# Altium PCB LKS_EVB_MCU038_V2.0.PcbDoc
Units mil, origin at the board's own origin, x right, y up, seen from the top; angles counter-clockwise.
Board outline 2625 x 1560 mil, 2 copper layers (Top Layer, Bottom Layer); 32 components, 46 nets, 145 pads, 22 vias.
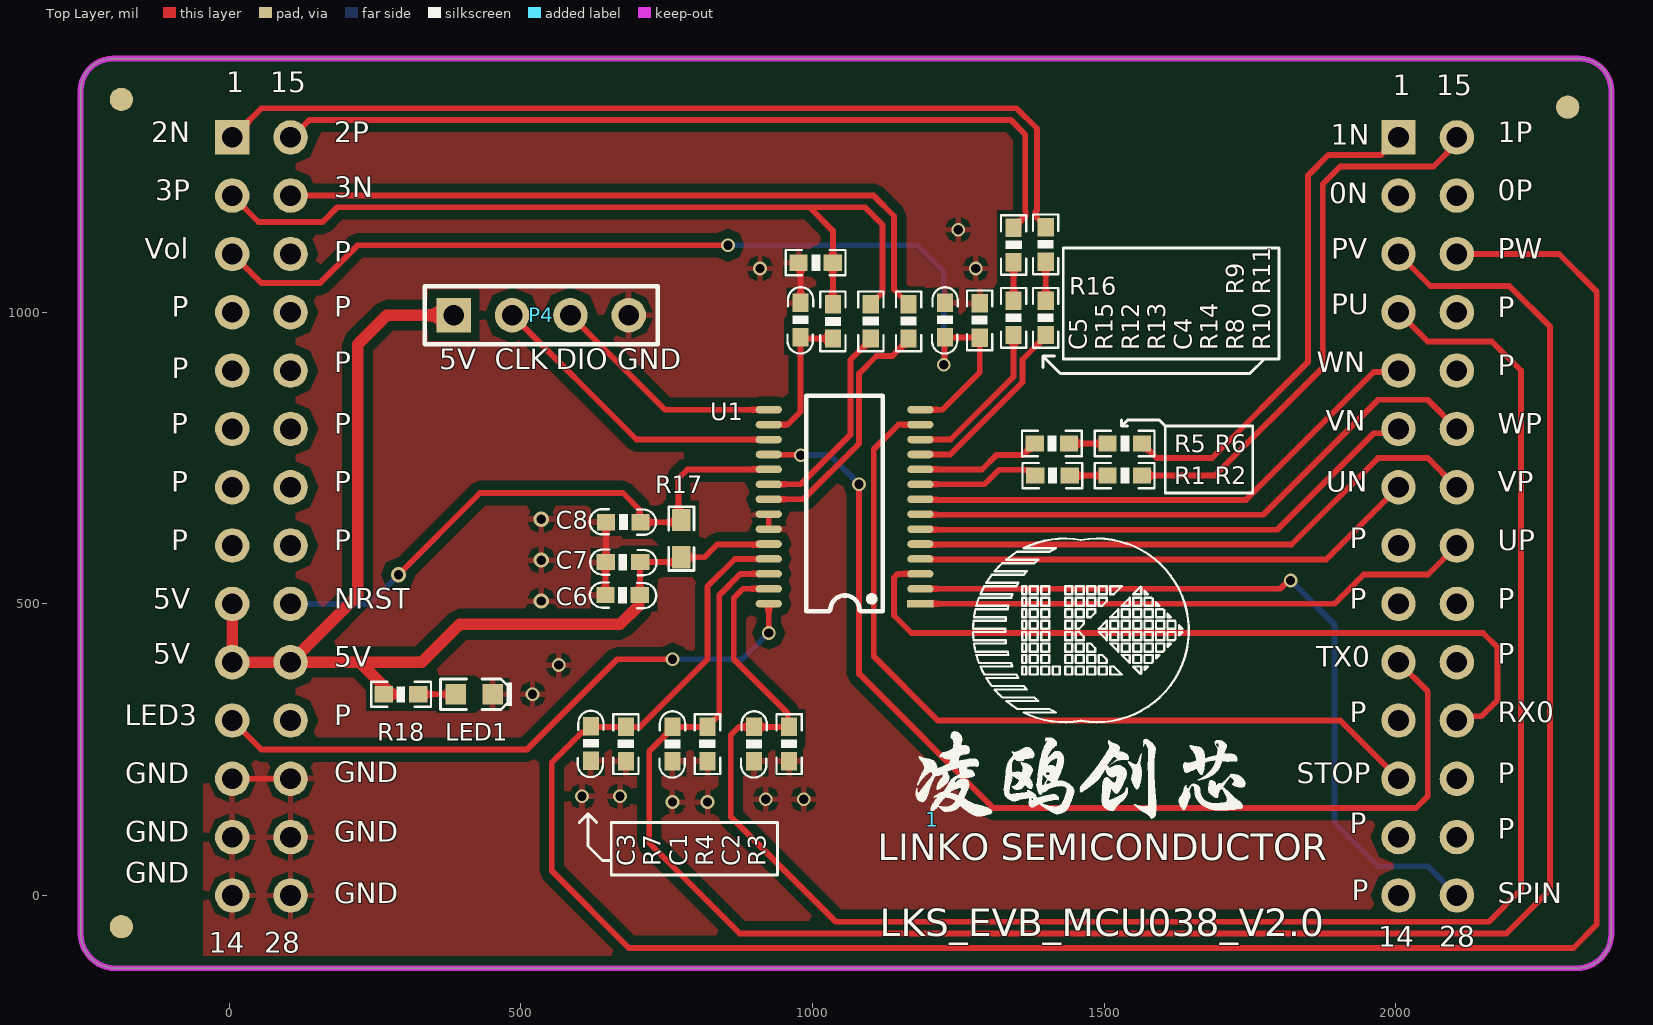
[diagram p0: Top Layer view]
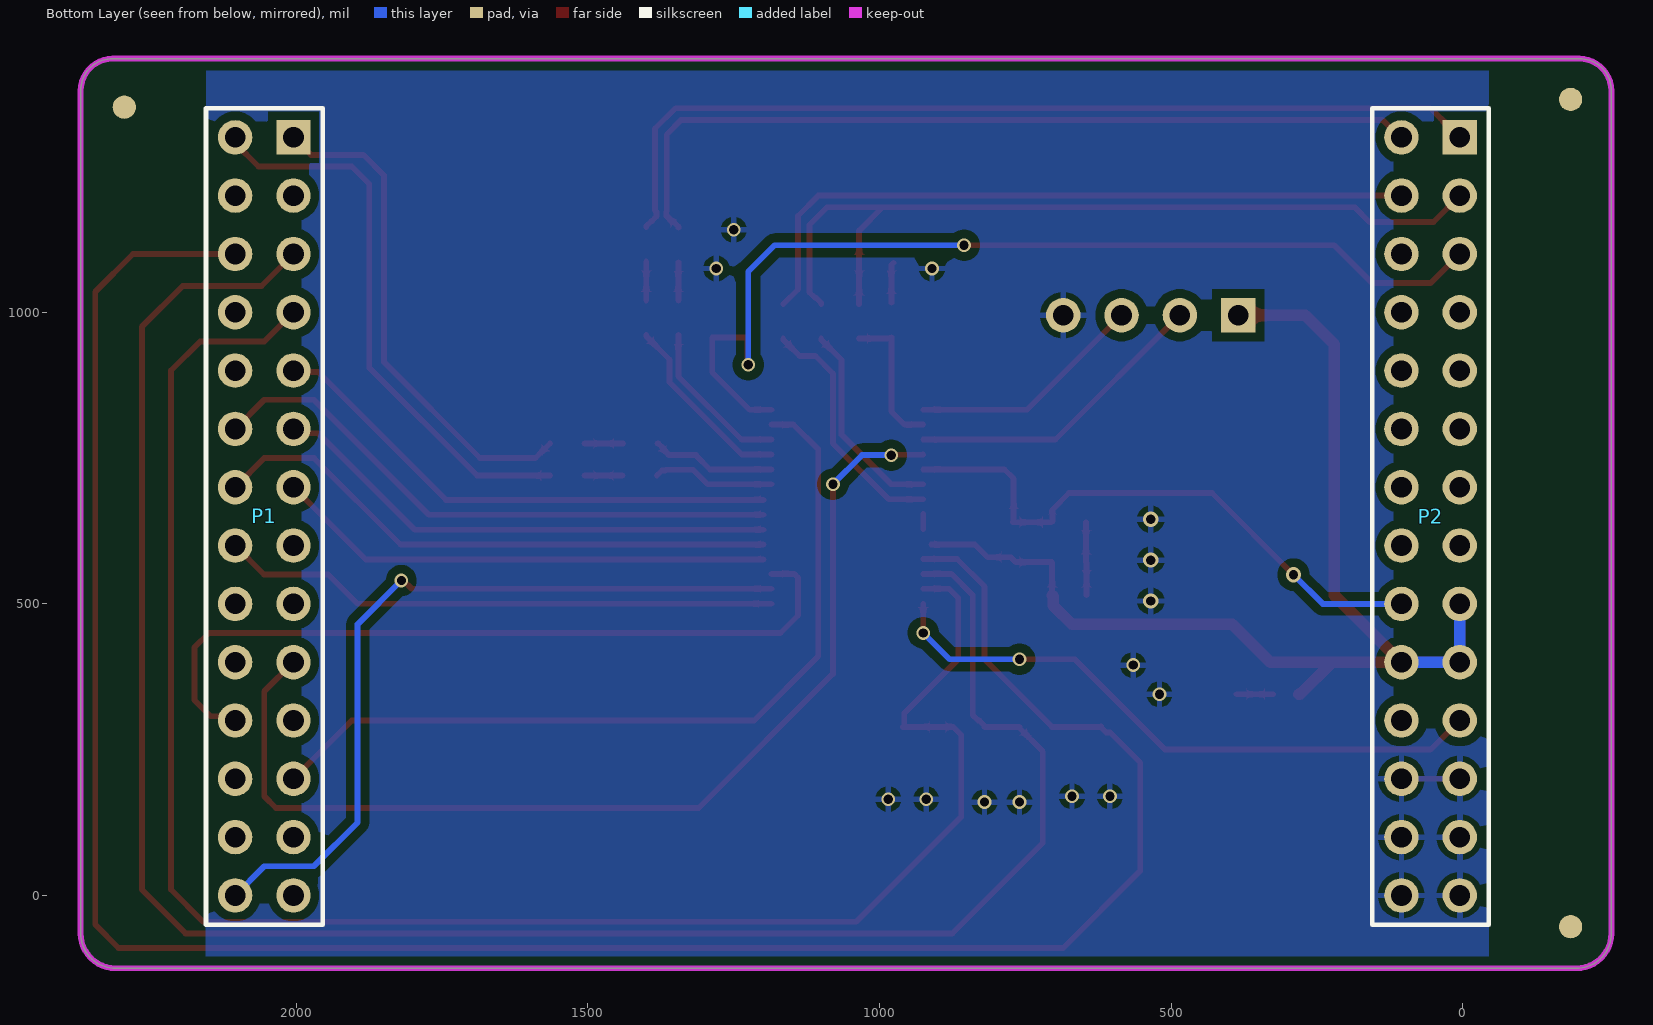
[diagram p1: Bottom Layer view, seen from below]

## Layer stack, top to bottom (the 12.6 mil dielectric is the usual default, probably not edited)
Top Solder: solder mask 0.4, Solder Resist, Dk 3.5
Top Layer: signal copper 1.4
Dielectric 1: dielectric 12.6, FR-4, Dk 4.8
Bottom Layer: signal copper 1.4
Bottom Solder: solder mask 0.4, Solder Resist, Dk 3.5

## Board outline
-255,-65 ccw(c-195,-65) -195,-125 2310,-125 ccw(c2310,-65) 2370,-65 2370,1380 ccw(c2315,1380) 2315,1435 -200,1435 ccw(c-200,1380) -255,1380

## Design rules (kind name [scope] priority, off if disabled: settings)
Clearance Clearance_1 [InPolygon] p1: gap=15 ignorepadtopadclearanceinfootprint=FALSE
Clearance [All] p2: gap=7.87 ignorepadtopadclearanceinfootprint=FALSE
ComponentClearance [All] p1: gap=0 collisioncheckmode=3 verticalgap=0 showdistances=FALSE
DiffPairsRouting DiffPair_DiffPairsRouting [All] p1: maxlimit=10 minlimit=10 mostfreqgap=10 toplayer_minwidth=10 toplayer_maxwidth=10 toplayer_prefwidth=10 bottomlayer_minwidth=10 bottomlayer_maxwidth=10 bottomlayer_prefwidth=10 maxuncoupledlength=500
DiffPairsRouting [All] p2: maxlimit=10 minlimit=10 mostfreqgap=10 toplayer_minwidth=15 toplayer_maxwidth=15 toplayer_prefwidth=15 bottomlayer_minwidth=15 bottomlayer_maxwidth=15 bottomlayer_prefwidth=15 maxuncoupledlength=500
MatchedLengths DiffPair_MatchedLengths [All] p1: tolerance=1000 checknetsindiffpair=TRUE checkdiffpairvsdiffpair=FALSE checkxsignals=FALSE checkothers=FALSE
PolygonConnect [All] p1: connectstyle=Relief reliefconductorwidth=10 reliefentries=4 polygonreliefangle="90 Angle" airgapwidth=10
RoutingVias [All] p1: holewidth=28 width=50 viastyle="Through Hole" minholewidth=28 minwidth=50 maxholewidth=28 maxwidth=50
SolderMaskExpansion [All] p1: expansion=4 istentingtop=FALSE
Width [All] p1: maxlimit=100 minlimit=1 preferedwidth=10
28 further rules are at their usual default settings.

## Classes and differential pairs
differential pair OPA2: +OPA2_P -OPA2_N

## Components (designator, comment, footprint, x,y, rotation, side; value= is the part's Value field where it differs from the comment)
1 "LKS_sign" LKS_LOGO2 1205,130 r0 top
C1 "1nF/16V" 0603C 760,289.06 r270 top
C2 "1nF/16V" 0603C 900,289.06 r270 top
C3 "1nF/16V" 0603C 620,290 r270 top
C4 "100nF/50V" 0603C 1227.36,1016.1 r270 top
C5 "1nF/50V" 0603C 979.71,1016.35 r270 top
C6 "10uF/10V" 0603C 645,515 r0 top
C7 "100nF/50V" 0603C 645.55,571.57 r0 top
C8 "100nF/50V" 0603C 705,640 r180 top
LED1 "LED" 0603D 420,345 r0 top
P1 "Header 14X2A" HDR2X14_CEN 2005,1300 r270 bottom
P2 "Header 14X2A" HDR2X14_CEN 5,1300 r270 bottom
P4 "Header 4" HDR1X4 385,995 r0 top
R1 "20K1%" 0603R#1 1440.94,720 r180 top value=K
R2 "20K1%" 0603R#1 1565,720 r180 top value=K
R3 "1K1%" 0603R#1 960,289.06 r270 top value=K
R4 "1K1%" 0603R#1 820,289.06 r270 top value=K
R5 "20K1%" 0603R#1 1440,775 r180 top value=K
R6 "20K1%" 0603R#1 1565,775 r180 top value=K
R7 "1K1%" 0603R#1 680,289.06 r270 top value=K
R8 "20K1%" 0603R#1 1345,1020 r270 top value=K
R9 "20K1%" 0603R#1 1345,1145 r270 top value=K
R10 "20K1%" 0603R#1 1400,1020 r270 top value=K
R11 "20K1%" 0603R#1 1400,1145.94 r270 top value=K
R12 "1K1%" 0603R#1 1100,1014.06 r270 top value=K
R13 "1K1%" 0603R#1 1165,1014.06 r270 top value=K
R14 "1K1%" 0603R#1 1286.81,1015.71 r270 top value=K
R15 "1K1%" 0603R#1 1035,955 r90 top value=K
R16 "10R" 0603R#1 1035,1085 r180 top value=K
R17 "20K1%" 0603R#2 775,612 r270 top value=K
R18 "330R" 0603R#1 265,345 r0 top value=330
U1 "037E" TSSOP-28 1186.63,498.48 r180 top

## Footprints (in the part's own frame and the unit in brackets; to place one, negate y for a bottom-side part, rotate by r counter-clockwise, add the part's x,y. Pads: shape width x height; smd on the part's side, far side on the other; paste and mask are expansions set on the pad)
0603C [mm]
  rect 0.8x0.7 smd: 1(0,0) 2(1.5,0)
  silkscreen extent -0.68,-0.57 2.21,0.55
0603D [mm]
  rect 0.9x0.9 smd: 1(-0.813,0) 2(0.813,0)
  silkscreen extent -1.47,-0.66 1.65,0.66
0603R#1 [mm]
  rect 0.8x0.7 smd: 1(0,0) 2(1.5,0)
  silkscreen extent -0.55,-0.55 2.05,0.55
0603R#2 [mm]
  rect 0.965x0.813 smd: 1(-0.813,0) 2(0.813,0)
  silkscreen extent -1.38,-0.55 1.38,0.55
HDR1X4 [mm] "Connector; Header; 4 Position"
  rect 1.5x1.5 hole 0.9: 1(0,0)
  round 1.5 hole 0.9: 2(2.54,0) 3(5.08,0) 4(7.62,0)
  silkscreen extent -1.27,-1.27 8.89,1.27
HDR2X14_CEN [mm] "Connector; Header; 14x2 Position"
  rect 1.5x1.5 hole 0.9: 1(0,0)
  round 1.5 hole 0.9: 2(2.54,0) 3(5.08,0) 4(7.62,0) 5(10.16,0) 6(12.7,0) 7(15.24,0) 8(17.78,0) 9(20.32,0) 10(22.86,0) 11(25.4,0) 12(27.94,0) 13(30.48,0) 14(33.02,0) 15(0,-2.54) 16(2.54,-2.54) 17(5.08,-2.54) 18(7.62,-2.54) 19(10.16,-2.54) 20(12.7,-2.54) 21(15.24,-2.54) 22(17.78,-2.54) 23(20.32,-2.54) 24(22.86,-2.54) 25(25.4,-2.54) 26(27.94,-2.54) 27(30.48,-2.54) 28(33.02,-2.54)
  silkscreen extent -1.27,-3.81 34.29,1.27
LKS_LOGO2 [mil] "标?"
  silkscreen extent 70,167 440,482
TSSOP-28 [mil] "9.70x4.40x1.00 e=0.65（蒜米工坊）"
  rect 45x12.99 smd: 1(1.63,-1.8)
  oval 45x12.99 smd: 2(1.63,-27.39) 3(1.63,-52.98) 4(1.63,-78.57) 5(1.63,-104.16) 6(1.63,-129.75) 7(1.63,-155.34) 8(1.63,-180.93) 9(1.63,-206.52) 10(1.63,-232.11) 11(1.63,-257.7) 12(1.63,-283.29) 13(1.63,-308.88) 14(1.63,-334.47) 15(261.47,-334.47) 16(261.47,-308.88) 17(261.47,-283.29) 18(261.47,-257.7) 19(261.47,-232.11) 20(261.47,-206.52) 21(261.47,-180.93) 22(261.47,-155.34) 23(261.47,-129.75) 24(261.47,-104.16) 25(261.47,-78.57) 26(261.47,-52.98) 27(261.47,-27.39) 28(261.47,-1.8)
  silkscreen extent 66,-358 197,11, body extent 2,-360 254,26, height 41

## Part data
C1 C2 C3: library part CAP, "Capacitor"
C4 C5 C6 C7 C8: library part C, "Capacitor"
LED1: "LED_Light"
P1 P2: "Header, 14-Pin, Dual row"
P4: "Header, 4-Pin"
R1 R2 R3 R4 R5 R6 R7 R8 R9 R10 R11 R12 R13 R14 R15 R16 R17 R18: library part Res, "Resistor"
U1: library part LKS32MC038Y6P8, "CHIP--TSSOP28"

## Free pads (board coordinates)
  round 40 all layers, no hole: 2(2295,1351.86) 3(-185,-53.57) 4(-185,1365)

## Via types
v1: diameter 23.62, hole 15.75, Top Layer to Bottom Layer, 18 vias
v2: diameter 26, hole 16, Top Layer to Bottom Layer, 4 vias

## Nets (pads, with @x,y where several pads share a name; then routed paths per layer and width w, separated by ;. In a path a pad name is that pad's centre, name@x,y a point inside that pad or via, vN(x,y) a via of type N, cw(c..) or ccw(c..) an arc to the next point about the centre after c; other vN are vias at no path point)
+5V: C6.2 C7.2 P2.9 P2.10 P2.24 P4.1 R17.2 R18.1 U1.24 | length 2190.1
  Top Layer w10: C6.2 704.06,571.02 C7.2 766.57,571.57 R17.2 815,580 836.61,601.61 U1.24@911.3,601.61
  Top Layer w20: P2.9 P2.10 P2.24 ; 280.94,345 278.98,345 223.98,400 ; P4.1 270,995 220,945 220,515 P2.24 ; C6.2 701.94,512.88 701.94,496.94 670,465 395,465 330,400 223.98,400 ; P2.24 223.98,400
  Bottom Layer w20: P2.9 P2.10 P2.24
GND: C1.2 C2.2 C3.2 C4.1 C5.1 C6.1 C7.1 C8.2 LED1.2 P2.12 P2.13 P2.14 P2.26 P2.27 P2.28 P4.4 R3.2 R4.2 R7.2 R14.1 R16.2 U1.22 U1.23 | length 321.2
  Top Layer w10: P2.12 P2.26 ; C6.1 645,571.02 C7.1 645.94,571.97 C8.2 ; U1.23 U1.22 ; R16.2 979.71,1081.24 C5.1
  other v1: 760,160 820,160 920,165 985,165 605,170 670,170 520,345 565,395 910,1075 1280,1075 1250,1141.54
  other v2: 535,505 535,575 535,645
GND0: P2.16 R13.1 | length 1210.8
  Top Layer w10: P2.16 1105,1200 1140,1165 1140,1039.06 R13.1
HALL_U: P2.8
HALL_V: P2.7
HALL_W: P2.6
HU: P2.21
HV: P2.20
HW: P2.19
LED3: P2.11 U1.28 | length 1074.1
  Top Layer w10: P2.11 55,250 510,250 665,405 v1(760,405) ; v1@925,450 v1(925.16,450.16) U1.28
  Bottom Layer w10: v1(760,405) 880,405 v1(925.16,450.16)
NetLED1_1: LED1.1 R18.2 | length 63
  Top Layer w10: R18.2@325,345 LED1.1
NetR1_1: R1.1 R2.2 | length 65
  Top Layer w10: R1.1 R2.2
NetR5_1: R5.1 R6.2 | length 65.9
  Top Layer w10: R5.1 R6.2
NetR8_1: R8.1 R9.2 | length 65.9
  Top Layer w10: R8.1 R9.2
NetR10_1: R10.1 R11.2 | length 66.9
  Top Layer w10: R10.1 R11.2
NRST: C8.1 P2.23 R17.1 U1.19 | length 1014.2
  Top Layer w10: v2(290,550) 430,690 675,690 703.58,661.42 703.58,641.42 C8.1 771,640 770,641 770,715 785.59,730.59 U1.19
  Bottom Layer w10: P2.23 240,500 v2(290,550)
OC: C5.2 R15.1 U1.16 | length 247.6
  Top Layer w10: U1.16 957.36,807.36 979.71,829.71 C5.2 982,955 R15.1
OPA0_IN: R13.2 U1.21 | length 425.4
  Top Layer w10: U1.21 984.41,679.41 1080,775 1080,895 1110,925 1136.97,925 1165,953.03 R13.2
OPA0_IP: R12.2 U1.20 | length 354.5
  Top Layer w10: U1.20 980,705 1065,790 1065,918.03 1100,953.03 R12.2
OPA2_N: R5.2 U1.10 | length 215.5
  Top Layer w10: U1.10 1290.59,730.59 1315,755 1360.94,755 1370.2,764.25 1370.2,766.22 1378.98,775 R5.2
OPA2_P: R1.2 U1.9 | length 211.4
  Top Layer w10: U1.9 1295,705 1320,730 1365.91,730 1367.13,728.78 1373.11,728.78 R1.2
OPA3_IN: R10.2 U1.11 | length 323.8
  Top Layer w10: U1.11 1236.18,756.18 1360,880 1360,918.98 1400,958.98 R10.2
OPA3_IP: R8.2 U1.12 | length 275.8
  Top Layer w10: U1.12 1236.77,781.77 1345,890 R8.2
PGND: P2.2 R12.1 R15.2 R16.1 | length 1484.3
  Top Layer w10: P2.2 50,1155 160,1155 185,1180 995,1180 ; R15.2 R16.1 1035,1140 995,1180 ; R12.1 1100,1016.02 1108.78,1024.8 1110.75,1024.8 1120,1034.06 1120,1150 1090,1180 995,1180
PGND0: P1.2
PGND1: P1.1 R6.1 | length 865.6
  Top Layer w10: R6.1 1590,750 1685,750 1850,915 1850,1235 1885,1270 1975,1270 P1.1
PGND2: P2.1 R11.1 | length 1593.2
  Top Layer w10: P2.1 55,1350 1350,1350 1385,1315 1385,1174.57 1382.38,1171.95 1382.38,1164.55 1390.24,1156.69 1391.22,1156.69 1400,1147.91 R11.1
PU: C2.1 P1.4 R3.1 U1.27 | length 3166.6
  Top Layer w10: U1.27 880.87,525.87 865,510 865,405 957.56,312.44 957.56,291.5 R3.1 C2.1 874.06,289.06 860,275 860,135 1040,-45 2160,-45 2215,10 2215,900 2165,950 2055,950 P1.4
PV: C1.1 P1.3 R4.1 U1.26 | length 3528.3
  Top Layer w10: U1.26 876.46,551.46 840,515 840,309.06 830.75,299.8 828.78,299.8 820,291.02 R4.1 C1.1 760,287.09 720,247.09 720,90 875,-65 2190,-65 2265,10 2265,975 2195,1045 2060,1045 P1.3
PW: C3.1 P1.17 R7.1 U1.25 | length 3993.2
  Top Layer w10: U1.25 867.05,577.05 820,530 820,405 704.06,289.06 620.94,289.06 C3.1 620,288.03 611.22,279.25 604.25,279.25 552.84,227.84 552.84,42.16 685,-90 2305,-90 2345,-50 2345,1035 2280,1100 P1.17
RXD0: P1.25 U1.3 | length 1350
  Top Layer w10: U1.3 1146.46,551.46 1140,545 1140,480 1170,450 2150,450 2175,425 2175,335 2147.4,307.4 2112.4,307.4 P1.25 P1.25@2110,300
SPIN: P1.28 U1.2 | length 1348.7
  Top Layer w10: U1.2 1802.18,525.87 1816.31,540 v1(1820,540)
  Bottom Layer w10: v1(1820,540) 1895,465 1895,125 1970,50 2055,50 P1.28
STOP1: P1.12 U1.13 | length 1439.5
  Top Layer w10: U1.13 1147.36,807.36 1105,765 1105,410 1215,300 1905,300 P1.12
SWCLK: P4.2 U1.17 | length 538.5
  Top Layer w10: P4.2@485,1005 P4.2 698.23,781.77 U1.17
SWDIO: P4.3 U1.15 | length 407.3
  Top Layer w10: P4.3 747.05,832.95 U1.15
TXD0: P1.10 U1.18 | length 1830.3
  Top Layer w10: U1.18 925.73,755.61 979.39,755.61 v1(980,755) ; v1(1080,705) 1080,380 1310,150 2035,150 2055,170 2055,350 P1.10
  Bottom Layer w10: v1(980,755) 1030,755 v1(1080,705)
UN: P1.7 U1.4 | length 857.7
  Top Layer w10: U1.4@1198.7,576.02 1881.02,576.02 P1.7
UP: P1.22 U1.1 | length 961.3
  Top Layer w10: U1.1 1895.27,500.28 1945.43,550.43 2055.43,550.43 P1.22
UP-: P2.15 R9.1 | length 1452.8
  Top Layer w10: P2.15 107.56,1300 137.56,1330 1340,1330 1365,1305 1365,1172.73 1365.66,1172.07 1365.66,1165.66 1355.75,1155.75 1353.78,1155.75 1345,1146.97 R9.1
VN: P1.6 U1.6 | length 877.9
  Top Layer w10: U1.6@1198.7,627.2 1797.2,627.2 1962.6,792.6 1997.6,792.6 P1.6
VOL_ADC: C4.2 P2.3 R14.2 U1.14 | length 1742
  Top Layer w10: P2.3 55,1050 155,1050 220,1115 v1(855,1115) ; U1.14 1222.95,832.95 1286.81,896.81 R14.2 1286.42,957.05 C4.2 1226.18,955.87 1226.18,911.18 v1(1225,910)
  Bottom Layer w10: v1(855,1115) 1180,1115 1225,1070 v1(1225,910)
VP: P1.21 U1.5 | length 988.5
  Top Layer w10: U1.5@1198.7,601.61 1821.61,601.61 1970,750 2055,750 P1.21
VP-: P1.15 R2.1 | length 970.6
  Top Layer w10: R2.1 1690,720 1875,905 1875,1220 1905,1250 2065,1250 2105,1290 P1.15
WN: P1.5 U1.8 | length 898.1
  Top Layer w10: U1.8@1198.7,678.39 1743.39,678.39 1962.6,897.6 2002.6,897.6 P1.5
WP: P1.20 U1.7 | length 1008.7
  Top Layer w10: U1.7@1198.7,652.8 1772.8,652.8 1970,850 2055,850 P1.20
WP-: P1.16
pads on no net: P1.8 P1.9 P1.11 P1.13 P1.14 P1.18 P1.19 P1.23 P1.24 P1.26 P1.27 P2.4 P2.5 P2.17 P2.18 P2.22 P2.25

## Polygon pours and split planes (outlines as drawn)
GND on Bottom Layer "GND_L02_P001" (solid, remove dead copper, pour order 1): -45,-125 2155,-125 2155,1435 -45,1435
GND on Top Layer "GND_L01_P004" (solid, remove dead copper, pour order 4): -45,-125 -45,1435 2155,1435 2155,-125

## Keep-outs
Keep-Out Layer:
  the board outline again, w10

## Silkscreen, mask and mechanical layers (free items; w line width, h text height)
Top Overlay:
  drawing of 38 lines, arcs and shapes, not listed
  text "2N" at -133.73,1280 h60
  text "2P" at 180,1280 h60
  text "1P" at 2175.06,1280 h60
  text "1N" at 1888.64,1275 h60
  text "3N" at 179.94,1185 h60
  text "3P" at -126.62,1180 h60
  text "0P" at 2175,1180 h60
  text "0N" at 1885.92,1175 h60
  text "Vol" at -144.61,1080 h60
  text "PV" at 1889.42,1080 h60
  text "PW" at 2175.06,1080 h60
  text "P" at 180,1075 h60
  text "PU" at 1889.86,985 h60
  text "P" at -98.71,980 h60
  text "P" at 180,980 h60
  text "P" at 2175.06,979.33 h60
  text "5V" at 360,890 h60
  text "CLK" at 455,890 h60
  text "DIO" at 560,890 h60
  text "GND" at 665,890 h60
  text "P" at 180,885 h60
  text "WN" at 1865,885 h60
  text "P" at 2175.06,880 h60
  text "P" at -98.71,875 h60
  text "VN" at 1880.26,785 h60
  text "P" at -100,780 h60
  text "P" at 180,780 h60
  text "WP" at 2175.06,780 h60
  text "P" at -100,680 h60
  text "P" at 180,680 h60
  text "UN" at 1880.65,680 h60
  text "VP" at 2175,680 h60
  text "P" at 1921.61,583.02 h60
  text "P" at -100,580 h60
  text "P" at 180,580 h60
  text "UP" at 2175,580 h60
  text "5V" at -130.4,480 h60
  text "NRST" at 180,480 h60
  text "P" at 1921.61,480 h60
  text "P" at 2175.06,480 h60
  text "5V" at -130.4,385 h60
  text "P" at 2175.06,385 h60
  text "5V" at 179.94,380 h60
  text "TX0" at 1864,380 h60
  text "P" at 1921.61,285 h60
  text "RX0" at 2175.06,285 h60
  text "LED3" at -178.91,280 h60
  text "P" at 180,280 h60
  text "GND" at 180,181.7 h60
  text "GND" at -178.07,180 h60
  text "STOP" at 1830.76,180 h60
  text "P" at 2175,180 h60
  text "P" at 1921.61,95 h60
  text "P" at 2175.06,85 h60
  text "GND" at -178.07,80 h60
  text "GND" at 180,80 h60
  text "GND" at -178.07,10 h60
  text "P" at 1925,-20 h60
  text "GND" at 180,-25 h60
  text "SPIN" at 2175,-25 h60
  text "LKS_EVB_MCU038_V2.0" at 1115,-85 h80
Top Solder:
  circle w78: c-185,1365 r17
  circle w78: c-185,-53.57 r17
  circle w78: c2295,1351.86 r17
